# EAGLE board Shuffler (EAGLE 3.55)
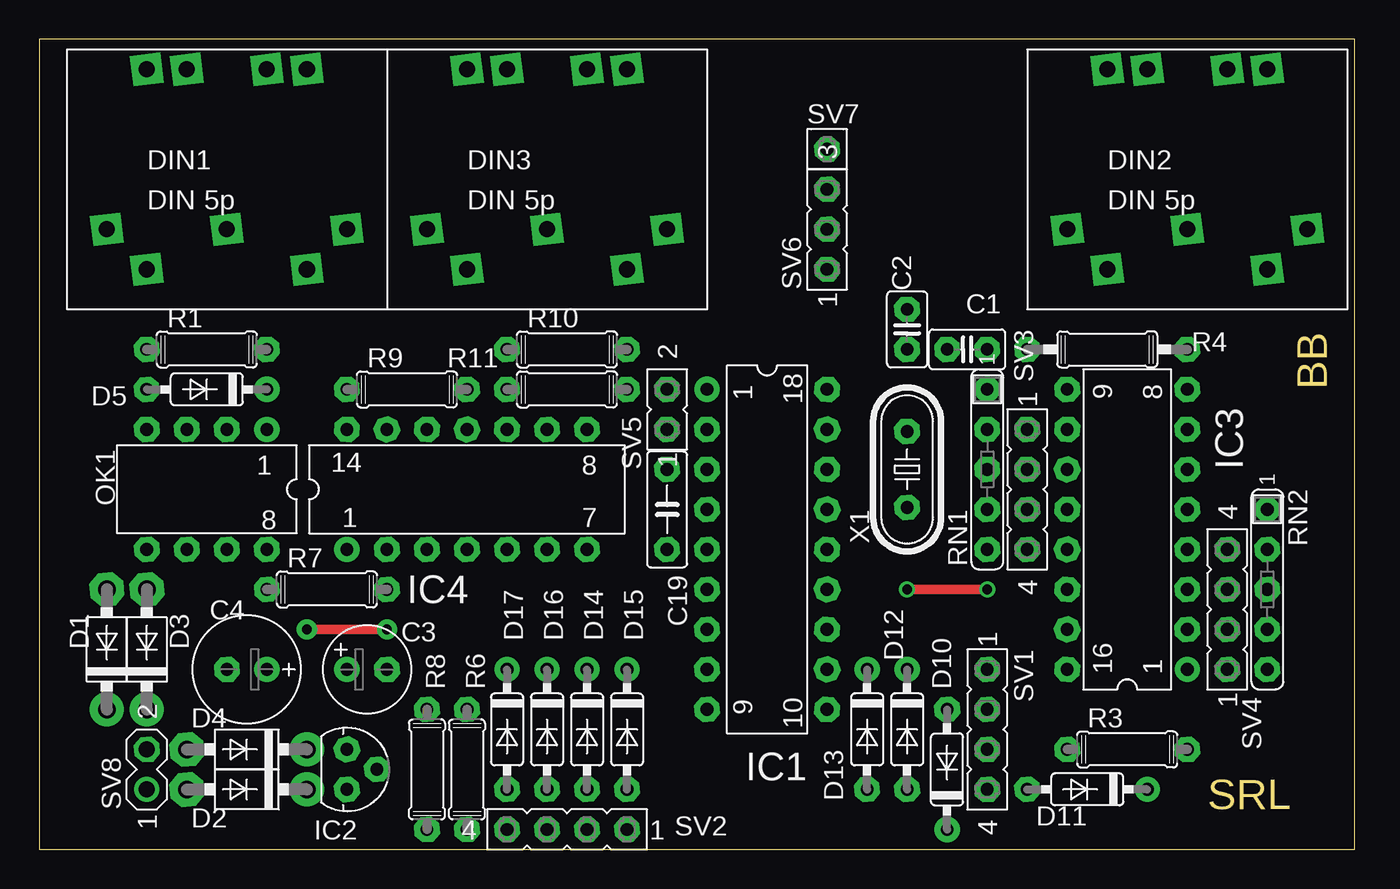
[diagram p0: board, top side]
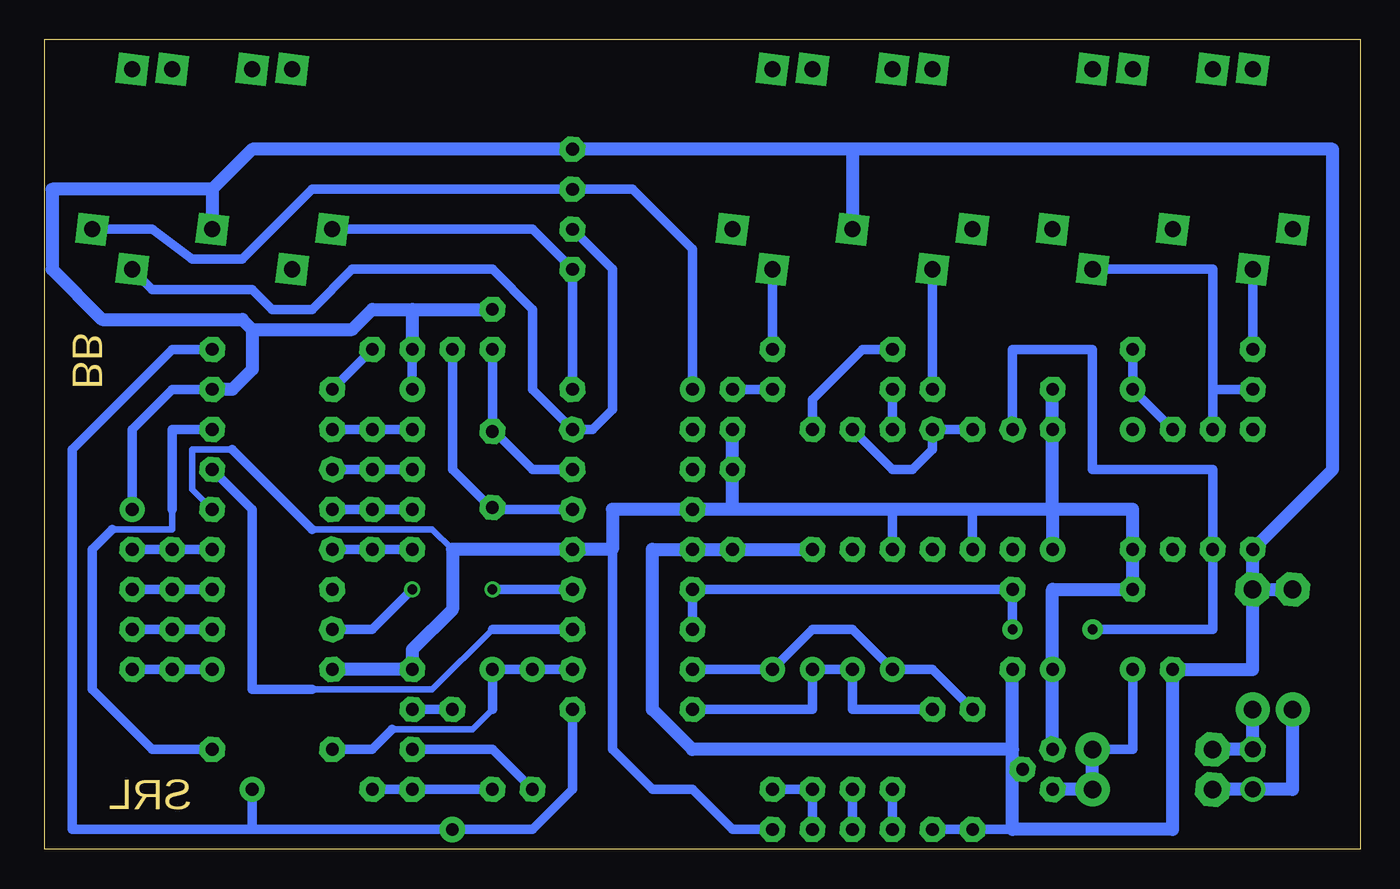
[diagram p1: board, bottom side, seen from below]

Size 83.49 x 51.42 mm. Coordinates in mm from the lower left corner, seen from the top.
Outline: 0,0 83.49,0 83.49,51.42 0,51.42 0,0
Copper layers used: Top, Bottom

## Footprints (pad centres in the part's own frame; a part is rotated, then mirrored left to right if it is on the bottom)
,5-2 = drill 0.813 pad 1.6 octagon:  -1.27,0;  1.27,0
,5-6 = drill 0.813 pad 1.6 octagon:  1.27,0 | drill 0.813 pad 1.6 round:  -1.27,0
,5-7 = drill 0.813 pad 1.6 octagon:  1.27,0 | drill 0.813 pad 1.6 round:  -1.27,0
B2,5 = drill 0.813 pad 1.6 octagon:  -2.54,0;  2.54,0
41-7 = drill 1.118 pad 2.159 round:  -3.81,0 | drill 1.118 pad 2.159 octagon:  3.81,0
35-7 = drill 0.813 pad 1.6 round:  -3.81,0 | drill 0.813 pad 1.6 octagon:  3.81,0
_PCB = drill 1.016 pad 1.93 square: 0 -5.08,10.16; 1 -2.54,10.16; 2 2.54,10.16; 3 5.08,10.16;  0,0;  -5.08,-2.54;  -7.62,0;  5.08,-2.54;  7.62,0
L18 = drill 0.813 pad 1.6 round:  -10.16,-3.81 | drill 0.813 pad 1.6 octagon:  -7.62,-3.81;  -5.08,-3.81;  -2.54,-3.81;  0,-3.81;  2.54,-3.81;  5.08,-3.81;  7.62,-3.81;  10.16,-3.81;  10.16,3.81;  7.62,3.81;  5.08,3.81;  2.54,3.81;  0,3.81;  -2.54,3.81;  -5.08,3.81;  -7.62,3.81;  -10.16,3.81
LXX = drill 0.813 pad 1.6 octagon:  -1.27,0;  0,1.905;  1.27,0
L16 = drill 0.813 pad 1.6 round:  -8.89,-3.81 | drill 0.813 pad 1.6 octagon:  -6.35,-3.81;  -3.81,-3.81;  -1.27,-3.81;  1.27,-3.81;  3.81,-3.81;  6.35,-3.81;  8.89,-3.81;  8.89,3.81;  6.35,3.81;  3.81,3.81;  1.27,3.81;  -1.27,3.81;  -3.81,3.81;  -6.35,3.81;  -8.89,3.81
L14 = drill 0.813 pad 1.6 round:  -7.62,-3.81 | drill 0.813 pad 1.6 octagon:  -5.08,-3.81;  -2.54,-3.81;  0,-3.81;  2.54,-3.81;  5.08,-3.81;  7.62,-3.81;  7.62,3.81;  5.08,3.81;  2.54,3.81;  0,3.81;  -2.54,3.81;  -5.08,3.81;  -7.62,3.81
L08 = drill 0.813 pad 1.6 round:  -3.81,-3.81 | drill 0.813 pad 1.6 octagon:  -1.27,-3.81;  1.27,-3.81;  3.81,-3.81;  3.81,3.81;  1.27,3.81;  -1.27,3.81;  -3.81,3.81
07/7 = drill 0.813 pad 1.6 octagon:  -3.81,0;  3.81,0
07/10 = drill 0.813 pad 1.6 octagon:  -5.08,0;  5.08,0
L5 = drill 0.813 pad 1.6 round:  -5.08,0 | drill 0.813 pad 1.6 octagon:  -2.54,0;  0,0;  2.54,0;  5.08,0
04-1 = drill 0.813 pad 1.6 octagon:  -3.81,0;  -1.27,0;  1.27,0;  3.81,0
02-1 = drill 0.813 pad 1.6 octagon:  -1.27,0;  1.27,0
03-1 = drill 0.813 pad 1.6 octagon:  -2.54,0;  0,0;  2.54,0
01-1 = drill 0.813 pad 1.6 octagon:  0,0
02-1' = drill 1.016 pad 1.6 round:  -1.27,0 | drill 1.016 pad 1.6 octagon:  1.27,0
49/S = drill 0.813 pad 1.6 octagon:  -2.413,0;  2.413,0

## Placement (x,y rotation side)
C1  33p  [,5-2]  58.89,31.75 180 top
C2  33p  [,5-2]  55.08,33.02 270 top
C3  100u/16V  [,5-6]  20.79,11.43 0 top
C4  100u/25V  [,5-7]  13.17,11.43 180 top
C19  100n  [B2,5]  39.84,21.58 270 top
D1  1N4001  [41-7]  4.28,12.69 90 top
D2  1N4001  [41-7]  13.17,3.81 180 top
D3  1N4001  [41-7]  6.82,12.69 90 top
D4  1N4001  [41-7]  13.17,6.35 180 top
D5  1N4148  [35-7]  10.63,29.21 180 top
D10  1N4148  [35-7]  57.62,5.07 90 top
D11  1N4148  [35-7]  66.51,3.81 180 top
D12  1N4148  [35-7]  55.08,7.61 270 top
D13  1N4148  [35-7]  52.54,7.61 270 top
D14  1N4148  [35-7]  34.76,7.61 270 top
D15  1N4148  [35-7]  37.3,7.61 270 top
D16  1N4148  [35-7]  32.22,7.61 270 top
D17  1N4148  [35-7]  29.68,7.61 270 top
DIN1  DIN 5p  [_PCB]  11.9,39.36 0 top
DIN2  DIN 5p  [_PCB]  72.86,39.36 0 top
DIN3  DIN 5p  [_PCB]  32.22,39.36 0 top
IC1  PIC16F84-10  [L18]  46.19,19.04 270 top
IC2  78L05  [LXX]  19.52,5.07 270 top
IC3  4532  [L16]  69.05,20.32 90 top
IC4  74HC14  [L14]  27.14,22.86 0 top
OK1  6N137  [L08]  10.63,22.86 180 top
R1  220  [07/7]  10.63,31.75 0 top
R3  2k  [07/7]  69.05,6.35 0 top
R4  2k  [07/10]  67.78,31.75 180 top
R6  4k7  [07/7]  27.14,5.07 90 top
R7  360  [07/7]  18.25,16.5 0 top
R8  4k7  [07/7]  24.6,5.07 90 top
R9  220  [07/7]  23.33,29.21 0 top
R10  220  [07/7]  33.49,31.75 0 top
R11  1k2  [07/7]  33.49,29.21 0 top
RN1  4x10k  [L5]  60.16,24.13 270 top
RN2  4x10k  [L5]  77.94,16.5 270 top
SV1  FE04-1  [04-1]  60.16,7.61 270 top
SV2  FE04-1  [04-1]  33.49,1.27 180 top
SV3  FE04-1  [04-1]  62.7,22.86 270 top
SV4  FE04-1  [04-1]  75.4,15.24 90 top
SV5  [02-1]  39.84,27.93 90 top
SV6  FE03-1  [03-1]  50,39.36 90 top
SV7  FE01-1  [01-1]  50,44.44 0 top
SV8  MA02-1  [02-1']  6.82,5.07 90 top
X1  10MHz  [49/S]  55.08,24.13 270 top

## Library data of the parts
C1 C2 C19 = CAP
C3 C4 = POLCAP
D1-D5 D10-D17 = DIODE
DIN1-DIN3 = con-din
IC1 = PIC
IC2 = V-REG
IC3 = 45XX
IC4 = 74XX
OK1 = OPTOCPL
R1 R3 R4 R6-R11 = R
RN1 RN2 = R-SIL
SV1-SV7 = CON-LSTA
SV8 = CON-LSTB
X1 = QUARTZ

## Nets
+15V: C4. D2. D4. IC2.
GND: C1. C2. C3. C4. C19. D1. D3. DIN2. DIN3. IC1. IC2. IC3. IC4. OK1. R6. R8. RN1. RN2. SV7.
N$1: IC1. IC3.
N$2: IC3. R3.
N$3: IC1. IC3.
N$4: D10. D11. IC1. R4.
N$5: D12. D13. IC1. R3.
N$6: R11. SV5.
N$8: D11. D12. SV1.
N$9: D10. SV1.
N$10: IC3. RN2. SV4.
N$11: D13. SV1.
N$12: D15. D17. IC1. R8.
N$13: D17. SV2.
N$14: D16. SV2.
N$15: D14. D15. SV2.
N$17: IC3. RN2. SV4.
N$18: D14. D16. IC1. R6.
N$19: IC3. RN2. SV4.
N$20: IC3. RN2. SV4.
N$21: IC3. RN1. SV3.
N$22: IC3. RN1. SV3.
N$23: IC3. RN1. SV3.
N$24: IC3. RN1. SV3.
N$25: IC3. R4.
N$26: DIN2. IC1. SV6.
N$27: DIN2. IC1. SV6.
N$28: IC4.
N$29: IC4. R10.
N$30: DIN3. R9.
N$31: DIN3. R10.
N$32: IC4. R11.
S$1: DIN1. R1.
S$2: D5. OK1. R1.
S$3: D5. DIN1. OK1.
S$5: DIN2. IC1. SV6.
S$31: IC1. IC4. OK1. R7.
S$32: C2. IC1. X1.
S$33: C1. IC1. X1.
S$65: D3. D4. SV8.
S$66: D1. D2. SV8.
VDD: C3. C19. IC1. IC2. IC3. IC4. OK1. R7. R9. SV1. SV2. SV5.

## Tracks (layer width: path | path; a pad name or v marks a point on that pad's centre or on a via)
+15V
  Bottom 0.61: C4. 14.44,6.35 16.98,6.35 16.98,3.81 IC2.
  Bottom 0.813: IC2. 16.98,3.81 16.98,6.35
GND
  Bottom 0.61: 6.82,19.04 D3. D1. | 22.06,5.07 21.42,5.07 | 34.76,19.04 C19. 42.38,19.04 | 27.14,1.27 24.6,1.27 22.06,1.27 | 60.16,31.75 60.16,29.21 | 77.94,21.58 77.94,26.67 75.4,29.21 72.86,29.21
  Bottom 0.813: 32.22,44.44 32.22,39.36 | 72.86,41.91 70.32,44.44 SV7. 32.22,44.44 | 32.22,44.44 1.74,44.44 1.74,24.13 6.82,19.04 D3. | 72.86,41.91 72.86,39.36 | 72.86,41.91 83.02,41.91 83.02,36.83 79.84,33.65 70.95,33.65 70.32,33.02 | 70.32,33.02 63.97,33.02 62.7,34.28 60.16,34.28 | 60.16,34.28 60.16,31.75 | 60.16,34.28 55.08,34.28 | 70.32,33.02 70.32,30.47 71.59,29.21 72.86,29.21 | D3. D1. | D3. 6.82,11.43 11.9,11.43 11.9,1.27 22.06,1.27 22.06,5.07 22.06,6.35 | 34.76,19.04 C19. 42.38,19.04 44.92,19.04 44.92,8.89 42.38,6.35 22.06,6.35 | 22.06,6.35 22.06,11.43
N$1
  Bottom 0.406: 55.08,13.96 58.89,10.15 66.51,10.15
  Bottom 0.61: 72.86,24.13 70.32,21.58 70.32,10.15 66.51,10.15 | 50,13.96 55.08,13.96
N$2
  Bottom 0.406: 79.21,20.32 75.4,20.32 75.4,21.58
  Bottom 0.61: 72.86,26.67 75.4,26.67 75.4,21.58 | R3. 76.67,6.35 80.48,10.15 80.48,19.04 79.21,20.32
N$3  (via drill 0.61 pad 1.02)
  Top 0.61: v55.08,16.5 v60.16,16.5
  Bottom 0.61: 65.24,13.96 62.7,13.96 v60.16,16.5 | 50,16.5 v55.08,16.5
N$4
  Bottom 0.61: 72.86,31.75 75.4,31.75 81.75,25.39 81.75,1.27 70.32,1.27 | 70.32,1.27 57.62,1.27 52.54,1.27 50,3.81 50,8.89 | 70.32,1.27 70.32,3.81
N$5
  Bottom 0.406: 55.08,8.89 56.35,7.61 61.43,7.61
  Bottom 0.61: 50,11.43 52.54,11.43 55.08,11.43 55.08,8.89 | 61.43,7.61 62.7,6.35 65.24,6.35
N$6
  Bottom 0.61: R11. SV5.
N$8
  Bottom 0.61: D12. SV1. D11.
N$9
  Bottom 0.61: D10. 60.16,8.89
N$10
  Bottom 0.61: 72.86,19.04 SV4. 77.94,19.04
N$11
  Bottom 0.61: D13. 55.08,6.35 60.16,6.35
N$12
  Bottom 0.61: R8. 27.14,11.43 29.68,11.43 32.22,13.96 34.76,13.96 37.3,11.43 42.38,11.43
N$13
  Bottom 0.61: SV2. D17.
N$14
  Bottom 0.61: 32.22,1.27 D16.
N$15
  Bottom 0.61: 34.76,1.27 D14. D15.
N$17
  Bottom 0.61: 72.86,16.5 75.4,16.5 77.94,16.5
N$18
  Bottom 0.61: 42.38,8.89 39.84,8.89 34.76,8.89 34.76,11.43 32.22,11.43 32.22,8.89 R6.
N$19
  Bottom 0.61: 72.86,13.96 75.4,13.96 77.94,13.96
N$20
  Bottom 0.61: 72.86,11.43 75.4,11.43 RN2.
N$21
  Bottom 0.61: 65.24,19.04 SV3. RN1.
N$22
  Bottom 0.61: 65.24,21.58 62.7,21.58 60.16,21.58
N$23
  Bottom 0.61: 65.24,24.13 62.7,24.13 60.16,24.13
N$24
  Bottom 0.61: 65.24,26.67 62.7,26.67 60.16,26.67
N$25
  Bottom 0.61: 65.24,29.21 R4.
N$26
  Bottom 0.61: 65.24,39.36 52.54,39.36 50,36.83 IC1.
N$27
  Bottom 0.61: DIN2. 76.67,39.36 74.13,37.46 70.95,37.46 66.51,41.91 SV6. 46.19,41.91 42.38,38.09 42.38,29.21
N$28
  Bottom 0.61: 24.6,26.67 27.14,26.67 27.14,25.39 28.41,24.13 29.68,24.13 32.22,26.67
N$29
  Bottom 0.61: 29.68,31.75 31.58,31.75 34.76,28.57 34.76,26.67
N$30
  Bottom 0.61: R9. 27.14,36.83
N$31
  Bottom 0.61: R10. 37.3,36.83
N$32
  Bottom 0.61: 29.68,26.67 29.68,29.21
S$1
  Bottom 0.61: 6.82,31.75 6.82,36.83
S$2
  Bottom 0.61: 11.9,26.67 14.44,29.21 R1.
S$3
  Bottom 0.61: D5. 9.36,29.21 | 9.36,29.21 9.36,26.67 | 16.98,36.83 9.36,36.83 9.36,29.21
S$5
  Bottom 0.61: 50,39.36 47.46,36.83 47.46,27.93 48.73,26.67 50,26.67 52.54,29.21 52.54,34.28 55.08,36.83 63.97,36.83 66.51,34.28 69.05,34.28 70.32,35.55 76.67,35.55 77.94,36.83
S$31  (via drill 0.61 pad 1.27)
  Top 0.61: v16.98,13.96 v22.06,13.96
  Bottom 0.406: 42.38,16.5 42.38,13.96
  Bottom 0.61: v16.98,13.96 9.36,13.96 9.36,19.04 9.36,24.13 16.98,24.13 16.98,31.75 22.06,31.75 22.06,26.67 | R7. v22.06,13.96 R7. | R7. 42.38,16.5 42.38,13.96
S$32
  Bottom 0.61: 50,24.13 52.54,24.13 55.08,26.67 | 55.08,26.67 55.08,26.54 | 55.08,26.67 C2.
S$33
  Bottom 0.61: 55.08,21.58 X1. | 50,21.58 55.08,21.58 | 55.08,21.58 57.62,24.13 C1.
S$65
  Bottom 0.61: D4. SV8. 6.82,8.89
  Bottom 0.813: 6.82,8.89 SV8. D4.
S$66
  Bottom 0.61: 6.82,3.81 D2.
  Bottom 0.813: D2. 6.82,3.81 4.28,3.81 4.28,8.89
VDD
  Bottom 0.406: 57.62,19.04 58.89,20.32 66.51,20.32 | 71.59,25.39 74.13,25.39 74.13,22.86 72.86,21.58
  Bottom 0.61: 19.52,21.58 24.6,21.58 | 24.6,21.58 29.68,21.58 | 39.84,21.58 29.68,21.58 | IC4. 19.52,29.21 | 19.52,6.35 C3. | 47.46,19.04 47.46,6.35 44.92,3.81 42.38,3.81 39.84,1.27 37.3,1.27 | 60.16,11.43 IC3. | 66.51,20.32 71.59,25.39 | 39.84,24.13 39.84,26.67 | 24.6,21.58 24.6,19.04 | 29.68,21.58 29.68,19.04 | 14.44,16.5 OK1. 14.44,16.5
  Bottom 0.813: 19.52,6.35 C3. 19.52,16.5 14.44,16.5 | 14.44,16.5 OK1. | 14.44,16.5 OK1. | OK1. 14.44,21.58 19.52,21.58 | 19.52,21.58 IC4. 19.52,29.21 | 19.52,21.58 19.52,19.04 | 19.52,21.58 39.84,21.58 | 39.84,21.58 39.84,24.13 39.84,26.67 | 39.84,21.58 42.38,21.58 47.46,21.58 47.46,19.04 50,19.04 57.62,19.04 57.62,15.24 60.16,12.69 60.16,11.43 IC3.

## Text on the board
Dimension: BB | SRL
